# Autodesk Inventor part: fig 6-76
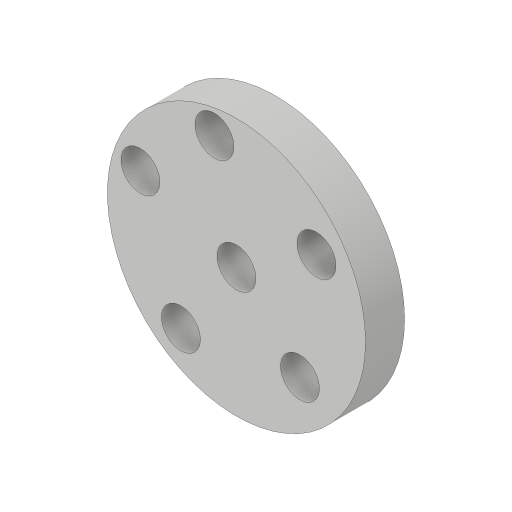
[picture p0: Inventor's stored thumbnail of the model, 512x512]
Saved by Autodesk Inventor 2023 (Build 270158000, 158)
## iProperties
Created: 2018-03
Part Number: fig 6-76
Material: Generic
Document SubType Name: Modeling
Designer: CADCIM 00
Density: 1 g/cm^3
Appearance: Default
Author: CADCIM 00
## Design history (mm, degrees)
sketch "Sketch1"
  geometry: C1 r 16.506 at (0, 0); 1 further point
  constraints: 1 centre point, 1 coincident
extrude "Extrusion1" new body sketch "Sketch1" distance "d0" = 5; taper "d1" = 0 deg
sketch "Sketch3"
  geometry: 2 further points
  constraints: 1 coincident
hole "Hole1" sketch "Sketch3" at (0, 0) diameter "d2" = 5; stored, may be unused: countersink angle "d6" = 90 deg, drill point angle "d8" = 118 deg; dims "d3" = 6, "d4" = 4, "d5" = 2, "d7" = 8
sketch "Sketch2"
  geometry: 6 further points
feature "Sketch Driven Pattern1" sketch "Sketch2"
body "Solid1"
